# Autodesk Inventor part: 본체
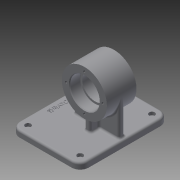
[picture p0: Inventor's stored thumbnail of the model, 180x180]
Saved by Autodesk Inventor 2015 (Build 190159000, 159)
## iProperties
Created: 2019-09
Part Number: 본체
Material: 일반
Document SubType Name: Modeling
Designer: now
Density: 1 g/cm^3
Appearance: 기본값
Mass: 205.415 g
Surface Area: 495.884 cm^2
Volume: 205.415 cm^3
Author: now
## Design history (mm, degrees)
sketch "스케치1"
  geometry: L1 (-49, 63)-(49, 63); L2 (49, 63)-(49, -63); L3 (49, -63)-(-49, -63); L4 (-49, -63)-(-49, 63); L5 (-49, 63)-(49, -63); L6 (49, 63)-(-49, -63); 1 further point
  constraints: 12 end point, 2 midpoint, 2 parallel, 1 horizontal, 1 perpendicular
  dimensions: "d0" = 98 distance of L2.end L3.end; "d1" = 126 distance of L1.end L2.end
extrude "돌출1" new body sketch "스케치1" distance "d2" = 9; taper "d3" = 0 deg
fillet "모깎기1" dims "d4" = 12
sketch "스케치2"
  geometry: A1 r 12 centre (-37, 51) between (-37, 63) and (-49, 51) reference; A2 r 12 centre (-37, -51) between (-49, -51) and (-37, -63) reference; A3 r 12 centre (37, -51) between (37, -63) and (49, -51) reference; A4 r 12 centre (37, 51) between (49, 51) and (37, 63) reference; 1 further point
hole "구멍1" sketch "스케치2" at (37, -51), (-37, -51), (-37, 51), (37, 51) diameter "d5" = 4.5; stored, may be unused: countersink angle "d9" = 90 deg, drill point angle "d11" = 118 deg; dims "d6" = 6, "d7" = 8, "d8" = 4.4, "d10" = 8
sketch "스케치3"
  geometry: L1 (-49, 51)-(-49, -51) reference; L2 (-19, -4)-(45, -4); L3 (45, -4)-(45, 4); L4 (45, 4)-(-19, 4); L5 (-19, 4)-(-19, -4); L6 (-19, -4)-(45, 4); L7 (45, -4)-(-19, 4); 3 further points
  constraints: 12 end point, 3 midpoint, 2 parallel, 1 horizontal, 1 horizontal alignment, 1 perpendicular
  dimensions: "d31" = 62 distance from line of L1 point (13, 0); "d32" = 4 distance from line of point (13, 0) L2; "d33" = 32 distance from line of L5 point (13, 0)
extrude "돌출2" join sketch "스케치3" distance "d15" = 50; taper "d16" = 0 deg
sketch "스케치4"
  geometry: L1 (49, -51)-(49, 51) reference; L2 (9, -17)-(17, -17); L3 (17, -17)-(17, 17); L4 (17, 17)-(9, 17); L5 (9, 17)-(9, -17); L6 (9, -17)-(17, 17); L7 (17, -17)-(9, 17); L8 (49, 51)-(49, -51) reference; 4 further points
  constraints: 12 end point, 4 midpoint, 2 parallel, 1 horizontal, 1 horizontal alignment, 1 perpendicular
  dimensions: "d28" = 36 distance from line of L1 point (13, 0); "d29" = 4 distance from line of L5 point (13, 0); "d30" = 34 distance of L2.end L3.end
extrude "돌출3" join sketch "스케치4" distance "d19" = 50; taper "d20" = 0 deg
fillet "모깎기2" dims "d21" = 3
fillet "모깎기5" dims "d34" = 3
fillet "모깎기6" dims "d35" = 3
sketch "스케치5" dims "d24" = 64
  geometry: L1 (22, 9)-(46, 9) reference; L2 (49, 6)-(49, 0) reference; L3 (49, 0)-(-49, 0) reference; L4 (-49, 0)-(-49, 6) reference; L5 (-45, 11.657)-(-45, 59) reference; L6 (-45, 59)-(19, 59) reference; L7 (19, 59)-(19, 12) reference; A1 r 3 centre (46, 6) between (49, 6) and (46, 9) reference; A2 r 3 centre (-48, 11.657) between (-47, 8.828) and (-45, 11.657) reference; A3 r 3 centre (22, 12) between (19, 12) and (22, 9) reference; A4 r 3 centre (-46, 6) between (-47, 8.828) and (-49, 6) reference; 3 further points
  constraints: 3 other
  dimensions: "d25" = 59 distance from line of L3 point (-13, 59); "d36" = 36 distance from line of point (-13, 59) L4
extrude "돌출4" join sketch "스케치5" stored distance "d26" = 42; taper "d27" = 0 deg
sketch "스케치6"
  geometry: C1 r 32 at (0, 0) reference; C2 r 21 at (0, 0); 1 further point
  constraints: 1 centre point, 1 coincident
  dimensions: "d37" = 42 diameter of C2
extrude "돌출5" cut sketch "스케치6" distance "d38" = 15; taper "d39" = 0 deg
sketch "스케치7"
  geometry: C1 r 32 at (0, 0) reference; C2 r 21 at (0, 0); 1 further point
  constraints: 1 centre point, 1 coincident
  dimensions: "d40" = 42 diameter of C2
extrude "돌출6" cut sketch "스케치7" distance "d41" = 15; taper "d42" = 0 deg
sketch "스케치8"
  geometry: C1 r 21 at (0, 0) reference; C2 r 18 at (0, 0); 1 further point
  constraints: 1 centre point, 1 coincident
  dimensions: "d43" = 36 diameter of C2
extrude "돌출7" cut sketch "스케치8" stored distance "d44" = 15; taper "d45" = 0 deg
fillet "모깎기7" dims "d46" = 0.3
sketch "스케치9"
  geometry: C1 r 21 at (0, 0) reference; 2 further points
  constraints: 1 vertical alignment
  dimensions: "d47" = 26 distance of C1.centre point (0, -26)
hole "구멍2" sketch "스케치9" at (0, -26) diameter "d48" = 3.242; stored, may be unused: countersink angle "d52" = 90 deg, drill point angle "d54" = 118 deg; dims "d49" = 8, "d50" = 4, "d51" = 2, "d53" = 10
chamfer "모따기1" distance "d58" = 1; stored, may be unused: second distance "d59" = 2, angle "d60" = 45 deg
fillet "모깎기8" dims "d61" = 3
sketch "스케치10"
  geometry: L1 (37, 63)-(-37, 63) reference; L2 (-49, -51)-(-49, 51) reference; 2 further points
  constraints: 1 other
  dimensions: "d62" = 63 distance from line of L1 point (-39, 0); "d63" = 10 distance from line of L2 point (-39, 0)
feature "엠보싱1" sketch "스케치10" dims "d0" = 98, "d1" = 126, "d64" = 0.5, "d65" = 0
node "솔리드1"
pattern_circular "원형 패턴1" dims angle "d56" = 360 deg
mirror "대칭1"
node "절단 모서리 투영1"
